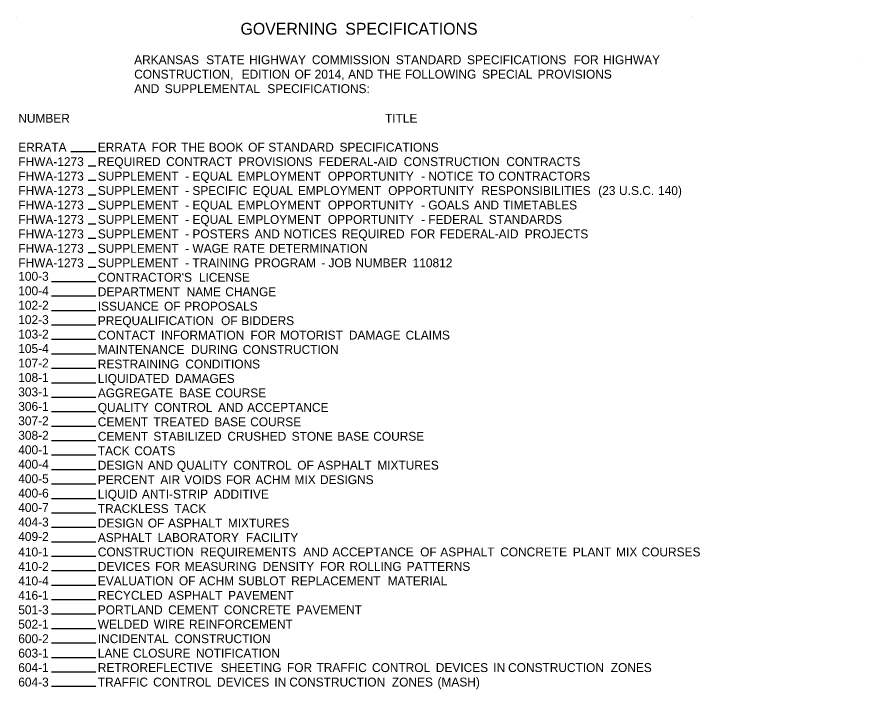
# Model space of a CAD drawing. Extents: x 200 to 2094, y 35 to 1167.
# Drawn here: x 200 to 767, y 537 to 990 of the extents above; entities that cross this region are included whole.
import ezdxf

# ---------------------------------------------------------------- set-up
doc = ezdxf.new("R2010")
doc.units = 0
doc.layers.add('Default', color=7, linetype='Continuous')
doc.layers.add('S_MISC_BOUNDARY', color=7, linetype='Continuous')

msp = doc.modelspace()

# ---------------------------------------------------------------- linework, layer by layer
at = {"layer": 'Default'}
for p, q in [((199.66, 989.74), (199.66, 989.74)), ((766.77, 959.69), (766.77, 959.69)), ((252.93, 899.23), (236.01, 899.23)), ((252.96, 889.48), (247.76, 889.48)), ((252.96, 879.73), (247.76, 879.73)), ((252.96, 869.98), (247.76, 869.98)), ((252.96, 860.23), (247.76, 860.23)), ((252.96, 850.48), (247.76, 850.48)), ((252.96, 840.73), (247.76, 840.73)), ((252.96, 830.98), (247.76, 830.98)), ((252.93, 821.23), (247.76, 821.23)), ((252.93, 811.48), (223.08, 811.48)), ((252.93, 801.73), (223.08, 801.73)), ((252.93, 791.98), (223.08, 791.98)), ((252.93, 782.23), (223.08, 782.23)), ((252.93, 772.48), (223.08, 772.48)), ((252.93, 762.73), (223.08, 762.73)), ((252.93, 752.98), (223.08, 752.98)), ((252.93, 743.23), (223.08, 743.23)), ((252.93, 733.48), (223.08, 733.48)), ((252.93, 723.73), (223.08, 723.73)), ((252.93, 713.98), (223.08, 713.98)), ((252.93, 704.23), (223.08, 704.23)), ((252.93, 694.48), (223.08, 694.48)), ((252.93, 684.73), (223.08, 684.73)), ((252.93, 674.98), (223.08, 674.98)), ((252.93, 665.23), (223.08, 665.23)), ((252.93, 655.48), (223.08, 655.48)), ((252.93, 645.73), (223.08, 645.73)), ((252.93, 635.98), (223.08, 635.98)), ((252.93, 626.23), (223.08, 626.23)), ((252.93, 616.48), (223.08, 616.48)), ((252.93, 606.73), (223.08, 606.73)), ((252.93, 596.98), (223.08, 596.98)), ((252.93, 587.23), (223.08, 587.23)), ((252.93, 577.48), (223.08, 577.48)), ((252.93, 567.73), (223.08, 567.73)), ((252.93, 557.98), (223.08, 557.98)), ((252.93, 548.23), (223.08, 548.23)), ((252.93, 538.48), (223.08, 538.48))]:
    msp.add_line(p, q, dxfattribs=at)
at = {"layer": 'S_MISC_BOUNDARY'}
msp.add_line((655.16, 990.23), (655.16, 990.23), dxfattribs=at)

# ---------------------------------------------------------------- texts
at = {"layer": 'Default'}
for s, height, p in [('GOVERNING', 8, (350.45, 978.18)), (' SPECIFICATIONS', 8, (418.1, 978.18)), ('           ARKANSAS', 6, (254.26, 958.28)), (' STATE', 6, (325.1, 958.28)), (' HIGHWAY', 6, (354, 958.28)), (' COMMISSION', 6, (396.32, 958.28)), (' STANDARD', 6, (452.92, 958.28)), (' SPECIFICATIONS', 6, (500.92, 958.28)), (' FOR', 6, (572.69, 958.28)), (' HIGHWAY', 6, (592.6, 958.28)), ('           CONSTRUCTION,', 6, (254.26, 948.53)), (' EDITION', 6, (348.99, 948.53)), (' OF', 6, (384.63, 948.53)), (' 2014,', 6, (398.22, 948.53)), (' AND', 6, (420.77, 948.53)), (' THE', 6, (440.35, 948.53)), (' FOLLOWING', 6, (459, 948.53)), (' SPECIAL', 6, (511.1, 948.53)), (' PROVISIONS', 6, (548.55, 948.53)), ('           AND', 6, (254.26, 938.78)), (' SUPPLEMENTAL', 6, (297.12, 938.78)), (' SPECIFICATIONS:', 6, (366.25, 938.78)), ('NUMBER', 6, (200.64, 918.79)), ('TITLE', 6, (447.82, 918.79)), ('ERRATA', 6, (200.64, 899.29)), ('ERRATA', 6, (254.26, 899.29)), (' FOR', 6, (288.29, 899.29)), (' THE', 6, (308.2, 899.29)), (' BOOK', 6, (326.85, 899.29)), (' OF', 6, (353.39, 899.29)), (' STANDARD', 6, (366.97, 899.29)), (' SPECIFICATIONS', 6, (414.97, 899.29)), ('FHWA-1273', 6, (200.64, 889.54)), ('REQUIRED', 6, (254.26, 889.54)), (' CONTRACT', 6, (298.07, 889.54)), (' PROVISIONS', 6, (346.81, 889.54)), (' FEDERAL-AID', 6, (400.87, 889.54)), (' CONSTRUCTION', 6, (458.19, 889.54)), (' CONTRACTS', 6, (527.37, 889.54)), ('FHWA-1273', 6, (200.64, 879.79)), ('SUPPLEMENT', 6, (254.26, 879.79)), (' EQUAL', 6, (315.79, 879.79)), (' EMPLOYMENT', 6, (346.24, 879.79)), (' OPPORTUNITY', 6, (407.1, 879.79)), (' NOTICE', 6, (474.78, 879.79)), (' TO', 6, (508.33, 879.79)), (' CONTRACTORS', 6, (521.93, 879.79)), (' -', 6, (310.93, 879.79)), (' -', 6, (469.92, 879.79)), ('FHWA-1273', 6, (200.64, 870.04)), ('SUPPLEMENT', 6, (254.26, 870.04)), (' SPECIFIC', 6, (315.79, 870.04)), (' EQUAL', 6, (356.45, 870.04)), (' EMPLOYMENT', 6, (386.9, 870.04)), (' OPPORTUNITY', 6, (447.76, 870.04)), (' RESPONSIBILITIES', 6, (510.58, 870.04)), (' (23', 6, (589.34, 870.04)), (' U.S.C.', 6, (603.4, 870.04)), (' 140)', 6, (629.68, 870.04)), (' -', 6, (310.93, 870.04)), ('FHWA-1273', 6, (200.64, 860.29)), ('SUPPLEMENT', 6, (254.26, 860.29)), (' -', 6, (310.93, 860.29)), (' EQUAL', 6, (315.79, 860.29)), (' EMPLOYMENT', 6, (346.24, 860.29)), (' OPPORTUNITY', 6, (407.1, 860.29)), (' -', 6, (469.92, 860.29)), (' GOALS', 6, (474.78, 860.29)), (' AND', 6, (505.55, 860.29)), (' TIMETABLES', 6, (525.14, 860.29)), ('FHWA-1273', 6, (200.64, 850.54)), ('SUPPLEMENT', 6, (254.26, 850.54)), (' EQUAL', 6, (315.79, 850.54)), (' EMPLOYMENT', 6, (346.24, 850.54)), (' OPPORTUNITY', 6, (407.1, 850.54)), (' FEDERAL', 6, (474.78, 850.54)), (' STANDARDS', 6, (515.48, 850.54)), (' -', 6, (310.93, 850.54)), (' -', 6, (469.92, 850.54)), ('FHWA-1273', 6, (200.64, 840.79)), ('SUPPLEMENT', 6, (254.26, 840.79)), (' POSTERS', 6, (315.79, 840.79)), (' AND', 6, (357.75, 840.79)), (' NOTICES', 6, (377.33, 840.79)), (' REQUIRED', 6, (416.49, 840.79)), (' FOR', 6, (462.62, 840.79)), (' FEDERAL-AID', 6, (482.53, 840.79)), (' PROJECTS', 6, (539.85, 840.79)), (' -', 6, (310.93, 840.79)), ('FHWA-1273', 6, (200.64, 831.04)), ('SUPPLEMENT', 6, (254.26, 831.04)), (' -', 6, (310.93, 831.04)), (' WAGE', 6, (315.79, 831.04)), (' RATE', 6, (343.29, 831.04)), (' DETERMINATION', 6, (367.53, 831.04)), ('FHWA-1273', 6, (200.64, 821.29)), ('SUPPLEMENT', 6, (254.26, 821.29)), (' -', 6, (310.93, 821.29)), (' TRAINING', 6, (315.79, 821.29)), (' PROGRAM', 6, (357.65, 821.29)), (' -', 6, (402.67, 821.29)), (' JOB', 6, (407.52, 821.29)), (' NUMBER', 6, (425.71, 821.29)), (' 110812', 6, (464.26, 821.29)), ('100-3', 6, (200.64, 812.21)), ("CONTRACTOR'S", 6, (254.26, 811.54)), (' LICENSE', 6, (320.17, 811.54)), ('100-4', 6, (200.64, 802.46)), ('DEPARTMENT', 6, (254.26, 801.79)), (' NAME', 6, (311.86, 801.79)), (' CHANGE', 6, (337.96, 801.79)), ('102-2', 6, (200.64, 792.71)), ('ISSUANCE', 6, (254.26, 792.04)), (' OF', 6, (296.68, 792.04)), (' PROPOSALS', 6, (310.27, 792.04)), ('102-3', 6, (200.64, 782.96)), ('PREQUALIFICATION', 6, (254.26, 782.29)), (' OF', 6, (335.1, 782.29)), (' BIDDERS', 6, (348.69, 782.29)), ('103-2', 6, (200.64, 773.21)), ('CONTACT', 6, (254.26, 772.54)), (' INFORMATION', 6, (294.62, 772.54)), (' FOR', 6, (354.94, 772.54)), (' MOTORIST', 6, (374.85, 772.54)), (' DAMAGE', 6, (421.26, 772.54)), (' CLAIMS', 6, (459.47, 772.54)), ('105-4', 6, (200.64, 763.46)), ('MAINTENANCE', 6, (254.26, 762.79)), (' DURING', 6, (314.84, 762.79)), (' CONSTRUCTION', 6, (349.71, 762.79)), ('107-2', 6, (200.64, 753.71)), ('RESTRAINING', 6, (254.26, 753.04)), (' CONDITIONS', 6, (311.03, 753.04)), ('108-1', 6, (200.64, 743.96)), ('LIQUIDATED', 6, (254.26, 743.29)), (' DAMAGES', 6, (304.12, 743.29)), ('303-1', 6, (200.64, 734.21)), ('AGGREGATE', 6, (254.26, 733.54)), (' BASE', 6, (306.93, 733.54)), (' COURSE', 6, (331.18, 733.54)), ('306-1', 6, (200.64, 724.46)), ('QUALITY', 6, (254.26, 723.79)), (' CONTROL', 6, (290.07, 723.79)), (' AND', 6, (333.09, 723.79)), (' ACCEPTANCE', 6, (352.67, 723.79)), ('307-2', 6, (200.64, 714.71)), ('CEMENT', 6, (254.26, 714.04)), (' TREATED', 6, (289.49, 714.04)), (' BASE', 6, (330.51, 714.04)), (' COURSE', 6, (354.76, 714.04)), ('308-2', 6, (200.64, 704.96)), ('CEMENT', 6, (254.26, 704.29)), (' STABILIZED', 6, (289.49, 704.29)), (' CRUSHED', 6, (339.36, 704.29)), (' STONE', 6, (382.7, 704.29)), (' BASE', 6, (413.46, 704.29)), (' COURSE', 6, (437.72, 704.29)), ('400-1', 6, (200.64, 695.21)), ('TACK', 6, (254.26, 694.54)), (' COATS', 6, (276.61, 694.54)), ('400-4', 6, (200.64, 685.46)), ('DESIGN', 6, (254.26, 684.79)), (' AND', 6, (285.72, 684.79)), (' QUALITY', 6, (305.3, 684.79)), (' CONTROL', 6, (343.44, 684.79)), (' OF', 6, (386.46, 684.79)), (' ASPHALT', 6, (400.05, 684.79)), (' MIXTURES', 6, (440.41, 684.79)), ('400-5', 6, (200.64, 675.71)), ('PERCENT', 6, (254.26, 675.04)), (' AIR', 6, (294.16, 675.04)), (' VOIDS', 6, (310.35, 675.04)), (' FOR', 6, (338.33, 675.04)), (' ACHM', 6, (358.24, 675.04)), (' MIX', 6, (384.62, 675.04)), (' DESIGNS', 6, (401.8, 675.04)), ('400-6', 6, (200.64, 665.96)), ('LIQUID', 6, (254.26, 665.29)), (' ANTI-STRIP', 6, (281.76, 665.29)), (' ADDITIVE', 6, (330.3, 665.29)), ('400-7', 6, (200.64, 656.21)), ('TRACKLESS', 6, (254.26, 655.54)), (' TACK', 6, (303.68, 655.54)), ('404-3', 6, (200.64, 646.46)), ('DESIGN', 6, (254.26, 645.79)), (' OF', 6, (285.72, 645.79)), (' ASPHALT', 6, (299.31, 645.79)), (' MIXTURES', 6, (339.68, 645.79)), ('409-2', 6, (200.64, 636.71)), ('ASPHALT', 6, (254.26, 636.04)), (' LABORATORY', 6, (292.3, 636.04)), (' FACILITY', 6, (351.87, 636.04)), ('410-1', 6, (200.64, 626.29)), ('CONSTRUCTION', 6, (254.26, 626.29)), (' REQUIREMENTS', 6, (321.11, 626.29)), (' AND', 6, (390.55, 626.29)), (' ACCEPTANCE', 6, (410.13, 626.29)), (' OF', 6, (469.32, 626.29)), (' ASPHALT', 6, (482.9, 626.29)), (' CONCRETE', 6, (523.27, 626.29)), (' PLANT', 6, (572.2, 626.29)), (' MIX', 6, (601.38, 626.29)), (' COURSES', 6, (618.56, 626.29)), ('410-2', 6, (200.64, 616.54)), ('DEVICES', 6, (254.26, 616.54)), (' FOR', 6, (290.63, 616.54)), (' MEASURING', 6, (310.54, 616.54)), (' DENSITY', 6, (363.12, 616.54)), (' FOR', 6, (401.72, 616.54)), (' ROLLING', 6, (421.64, 616.54)), (' PATTERNS', 6, (460.24, 616.54)), ('410-4', 6, (200.64, 606.79)), ('EVALUATION', 6, (254.26, 606.79)), (' OF', 6, (306.69, 606.79)), (' ACHM', 6, (320.28, 606.79)), (' SUBLOT', 6, (346.66, 606.79)), (' REPLACEMENT', 6, (382.36, 606.79)), (' MATERIAL', 6, (447.42, 606.79)), ('416-1', 6, (200.64, 597.04)), ('RECYCLED', 6, (254.26, 597.04)), (' ASPHALT', 6, (299.47, 597.04)), (' PAVEMENT', 6, (339.84, 597.04)), ('501-3', 6, (200.64, 587.29)), ('PORTLAND', 6, (254.26, 587.29)), (' CEMENT', 6, (299.47, 587.29)), (' CONCRETE', 6, (337.03, 587.29)), (' PAVEMENT', 6, (385.96, 587.29)), ('502-1', 6, (200.64, 577.54)), ('WELDED', 6, (254.26, 577.54)), (' WIRE', 6, (289.68, 577.54)), (' REINFORCEMENT', 6, (313.45, 577.54)), ('600-2', 6, (200.64, 567.79)), ('INCIDENTAL', 6, (254.26, 567.79)), (' CONSTRUCTION', 6, (303.81, 567.79)), ('603-1', 6, (200.64, 558.04)), ('LANE', 6, (254.26, 558.04)), (' CLOSURE', 6, (275.72, 558.04)), (' NOTIFICATION', 6, (318.13, 558.04)), ('604-1', 6, (200.64, 548.29)), ('RETROREFLECTIVE', 6, (254.26, 548.29)), (' SHEETING', 6, (334.87, 548.29)), (' FOR', 6, (379.54, 548.29)), (' TRAFFIC', 6, (399.45, 548.29)), (' CONTROL', 6, (436.84, 548.29)), (' DEVICES', 6, (479.86, 548.29)), (' IN', 6, (518.56, 548.29)), (' CONSTRUCTION', 6, (528.58, 548.29)), (' ZONES', 6, (597.76, 548.29)), ('604-3', 6, (200.64, 538.54)), ('TRAFFIC', 6, (254.26, 538.54)), (' CONTROL', 6, (289.33, 538.54)), (' DEVICES', 6, (332.35, 538.54)), (' IN', 6, (371.04, 538.54)), (' CONSTRUCTION', 6, (381.07, 538.54)), (' ZONES', 6, (450.25, 538.54)), (' (MASH)', 6, (481.02, 538.54))]:
    msp.add_text(s, height=height, dxfattribs=at).set_placement(p)

doc.saveas('drawing.dxf')
